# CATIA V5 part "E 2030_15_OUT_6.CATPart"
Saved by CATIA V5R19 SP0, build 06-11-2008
Material "Plastic": density 1200 kg/m3, Young's modulus 2.2e+09 Pa, Poisson ratio 0.38, thermal expansion 6.84e-05 1/K
Bounding box of the stored display mesh (mm): x 15.1 to 30.2, y -30.19 to -15.11, z -2 to 0
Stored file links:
  G:\UTB\Kombinované\Bakalářská práce\Catia\FORMA\E 2030_15_OUT_6.CATPart
  D:\Aplikace\CATIA\Nová složka\win_b64\startup\materials\Catalog.CATMaterial
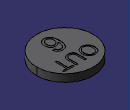
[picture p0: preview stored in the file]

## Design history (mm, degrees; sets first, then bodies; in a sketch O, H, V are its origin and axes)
Body1 "E 2030_15_OUT_1-8" (main body)
  Solid1: solid without history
